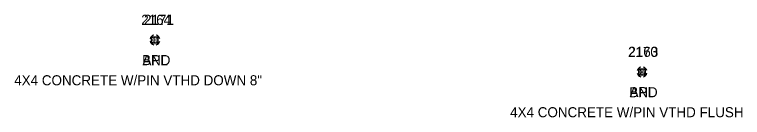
# Model space of a CAD drawing. Extents: x 1600395 to 1603269, y 874955 to 877143.
# Drawn here: x 1603124.4 to 1603269.5, y 875175.8 to 875196.2 of the extents above; entities that cross this region are included whole.
import ezdxf

# ---------------------------------------------------------------- set-up
doc = ezdxf.new("R2010")
doc.units = 0
for name, color, linetype in [('M_A', 7, 'Continuous'), ('M_C', 7, 'Continuous'), ('M_I', 7, 'Continuous'), ('MHBP', 7, 'Continuous'), ('MMP', 7, 'Continuous')]:
    doc.layers.add(name, color=color, linetype=linetype)

msp = doc.modelspace()

# ---------------------------------------------------------------- linework, layer by layer
at = {"layer": 'MHBP'}
for points in [[(1603151.69, 875191.83), (1603152.94, 875191.83), (1603152.94, 875190.58), (1603151.69, 875190.58)], [(1603248.79, 875185.46), (1603250.04, 875185.46), (1603250.04, 875184.21), (1603248.79, 875184.21)]]:
    msp.add_lwpolyline(points, close=True, dxfattribs=at)
for centre in [(1603152.32, 875191.2), (1603249.42, 875184.83)]:
    msp.add_circle(centre, 0.0833, dxfattribs=at)
at = {"layer": 'MMP'}
for p, q in [((1603151.75, 875191.83), (1603152.1, 875191.48)), ((1603151.75, 875190.56), (1603152.1, 875190.91)), ((1603151.78, 875191.2), (1603152.08, 875191.2)), ((1603152.38, 875191.5), (1603152.38, 875191.8)), ((1603152.38, 875190.6), (1603152.38, 875190.9)), ((1603152.66, 875191.48), (1603153.02, 875191.83)), ((1603152.66, 875190.91), (1603153.02, 875190.56)), ((1603152.68, 875191.2), (1603152.98, 875191.2)), ((1603248.82, 875185.5), (1603249.18, 875185.15)), ((1603248.86, 875184.86), (1603249.16, 875184.86)), ((1603249.46, 875185.16), (1603249.46, 875185.46)), ((1603249.74, 875185.15), (1603250.1, 875185.5)), ((1603249.76, 875184.86), (1603250.06, 875184.86)), ((1603248.82, 875184.23), (1603249.18, 875184.58)), ((1603249.46, 875184.26), (1603249.46, 875184.56)), ((1603249.74, 875184.58), (1603250.1, 875184.23))]:
    msp.add_line(p, q, dxfattribs=at)
for centre, start, end in [((1603152.38, 875191.2), 105, 165), ((1603152.38, 875191.2), 15, 75), ((1603152.38, 875191.2), 195, 255), ((1603152.38, 875191.2), 285, 345), ((1603249.46, 875184.86), 105, 165), ((1603249.46, 875184.86), 15, 75), ((1603249.46, 875184.86), 195, 255), ((1603249.46, 875184.86), 285, 345)]:
    msp.add_arc(centre, 1, start, end, dxfattribs=at)

# ---------------------------------------------------------------- texts
at = {"layer": 'M_A'}
for s, p in [('APL', (1603149.89, 875186.2)), ('BND', (1603149.81, 875186.2)), ('APL', (1603246.97, 875179.86)), ('BND', (1603246.91, 875179.83))]:
    msp.add_text(s, height=2, dxfattribs=at).set_placement(p)
at = {"layer": 'M_C'}
for s, p in [('4X4 CONCRETE W/PIN VTHD DOWN 8"', (1603124.33, 875182.2)), ('4X4 CONCRETE W/PIN VTHD FLUSH', (1603223.16, 875175.86))]:
    msp.add_text(s, height=2, dxfattribs=at).set_placement(p)
at = {"layer": 'M_I'}
for s, p in [('2164', (1603149.64, 875194.2)), ('2171', (1603150.19, 875194.2)), ('2170', (1603246.64, 875187.83)), ('2163', (1603246.72, 875187.86))]:
    msp.add_text(s, height=2, dxfattribs=at).set_placement(p)

doc.saveas('drawing.dxf')
